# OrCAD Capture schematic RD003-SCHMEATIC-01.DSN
size A3
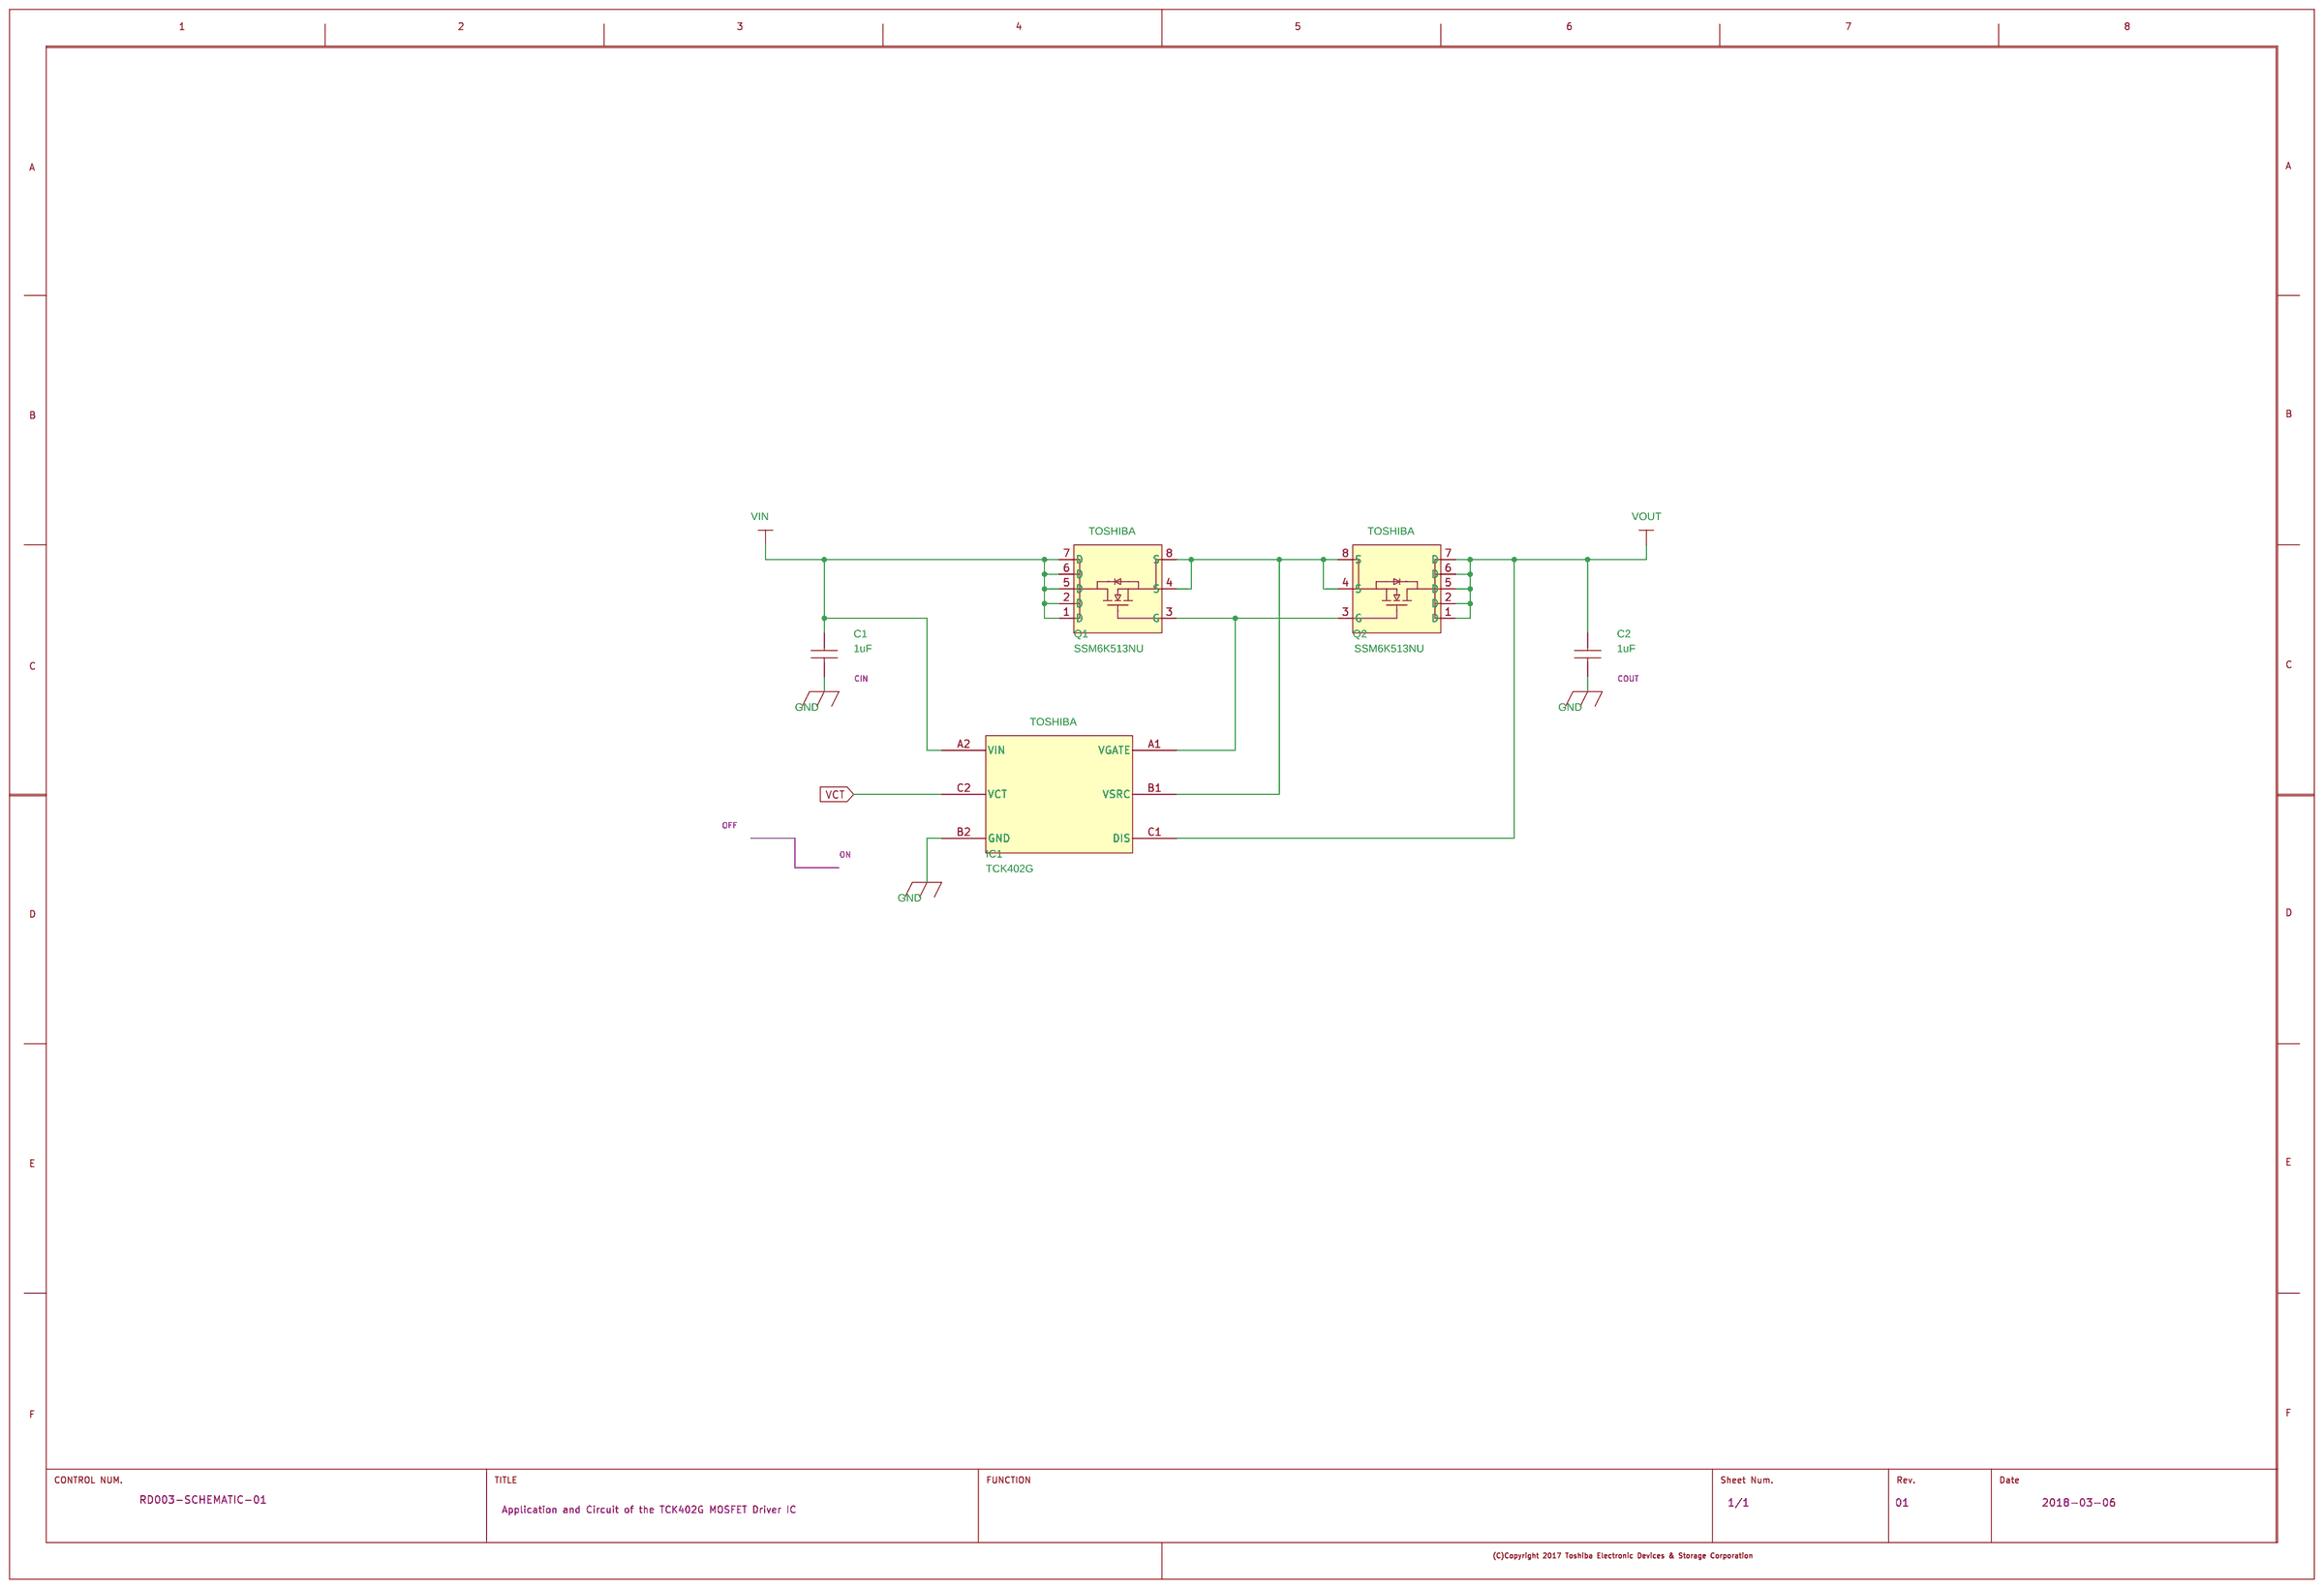
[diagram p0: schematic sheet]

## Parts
C1  1uF  [chip3216]
C2  1uF  [chip3216]
IC1  TCK402G  [WCSP6F]
Q1  SSM6K513NU  [UDFN6B]
Q2  SSM6K513NU  [UDFN6B]
U?#1  WAKU_DEF100

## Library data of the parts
C1 C2 = CAP_NP: Rating: 50V
IC1 = TCK402G: Manufacturer: TOSHIBA
Q1 Q2 = SSM6K513NU: Manufacturer: TOSHIBA
U?#1 = WAKU_DEF100: COMPONENTTYPE: 2; DATE: 2018-03-06; DRAWINGNUMBER: RD003-SCHEMATIC-01; FUNCTION: POWER block; REVISION: 01; SHEETNUMBER: 1/1; TITLE: Application and Circuit of the TCK402G MOSFET Driver IC; UPDATEDATE: 2018/03/02; UPDATETIME: 19:53:39; UPDATEUSER: f1043010

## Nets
GND: C1.2 C2.2 IC1.B2(GND)
VIN: C1.1 IC1.A2(VIN) Q1.1(D) Q1.2(D) Q1.5(D) Q1.6(D) Q1.7(D)
VCT: IC1.C2(VCT)
VOUT: C2.1 IC1.C1(DIS) Q2.1(D) Q2.2(D) Q2.5(D) Q2.6(D) Q2.7(D)
N13920086: IC1.A1(VGATE) Q1.3(G) Q2.3(G)
N13920096: IC1.B1(VSRC) Q1.4(S) Q1.8(S) Q2.4(S) Q2.8(S)

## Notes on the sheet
- CIN
- COUT
- OFF
- ON
